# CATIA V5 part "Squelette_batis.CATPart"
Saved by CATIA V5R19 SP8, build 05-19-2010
Part number: Squelette batis
Publications: "Droite.1", "Droite.2", "Droite.3", "Droite.4", "Droite.5", "Plan.1", "Plan.2", "Plan.3", "Plan.4"
Bounding box of the stored display mesh (mm): x -37 to 4, y -30 to 30, z -33.5 to 33.5
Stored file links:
  C:\Users\ThinkMotion\Desktop\EU_thinkMotion\iao\IAO_MMS_Groupe3\ecartoux\projet_IAO_ecartoux\projet_IAO_ecartoux\griffe_d'une_camera_ecartoux\Squelette_batis.CATPart
  C:\Users\ThinkMotion\Desktop\EU_thinkMotion\iao\IAO_MMS_Groupe3\ecartoux\projet_IAO_ecartoux\projet_IAO_ecartoux\griffe_d'une_camera_ecartoux\Squelette.CATProduct
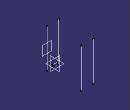
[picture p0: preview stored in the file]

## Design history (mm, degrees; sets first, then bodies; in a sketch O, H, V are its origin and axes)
Set1
  Point1: linked copy from another document
  Plane1: linked copy from another document
  Point2: linked copy from another document
  Plane2: linked copy from another document
  Point3 to Point5: linked copy from another document
  Plane3: linked copy from another document
Set2 "Set géométrique"
  Line1: type PtDir, RefPoint Point1, Direction Plane1, Start -4, End 5
  Line2: type PtDir, RefPoint Point2, Direction Plane2, Start -33.5, End 33.5
  Line3: type PtDir, RefPoint Point3, Direction Plane2, Start -33.5, End 33.5
  Line4: type PtDir, RefPoint Point4, Direction Plane2, Start -33.5, End 33.5
  Line5: type PtDir, RefPoint Point5, Direction Plane2, Start -33.5, End 33.5
  Plane4 "Plan.1": type Offset, RefPlane Plane2, Offset 0
  Plane5 "Plan.2": type Offset, RefPlane Plane1, Offset 0
  Plane6 "Plan.3": type Offset, RefPlane Plane3, Offset 0
  Plane7 "Plan.4": type 2Lines, Element1 Line2, Element2 Line3
Body1 (main body)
